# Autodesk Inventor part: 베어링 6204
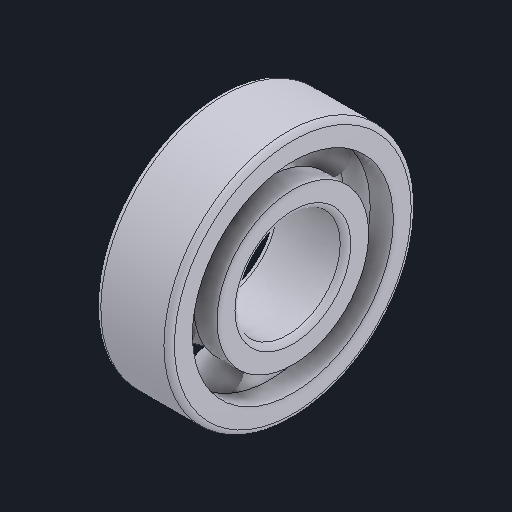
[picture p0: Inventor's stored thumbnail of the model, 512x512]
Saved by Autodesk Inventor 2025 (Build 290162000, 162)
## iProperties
Created: 2025-08
Part Number: 베어링 6204
Material: 강철, 연강
Description: 깊은 그루브 볼 베어링
Document SubType Name: Modeling
Designer: infra14
Density: 7.86 g/cm^3
Appearance: 기본값
Author: jhkim
Sending System: Autodesk Inventor 2026
Preprocessor: ST-DEVELOPER v20.1
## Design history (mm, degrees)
feature "Solid1"
feature "Solid1:1"
feature "Solid1:2"
feature "Solid1:3"
feature "Solid1:4"
feature "Solid1:5"
feature "Solid1:6"
feature "Solid1:7"
feature "Solid1:8"
node "솔리드1"
node "솔리드2"
node "솔리드3"
node "솔리드4"
node "솔리드5"
node "솔리드6"
node "솔리드7"
node "솔리드8"
node "솔리드9"
